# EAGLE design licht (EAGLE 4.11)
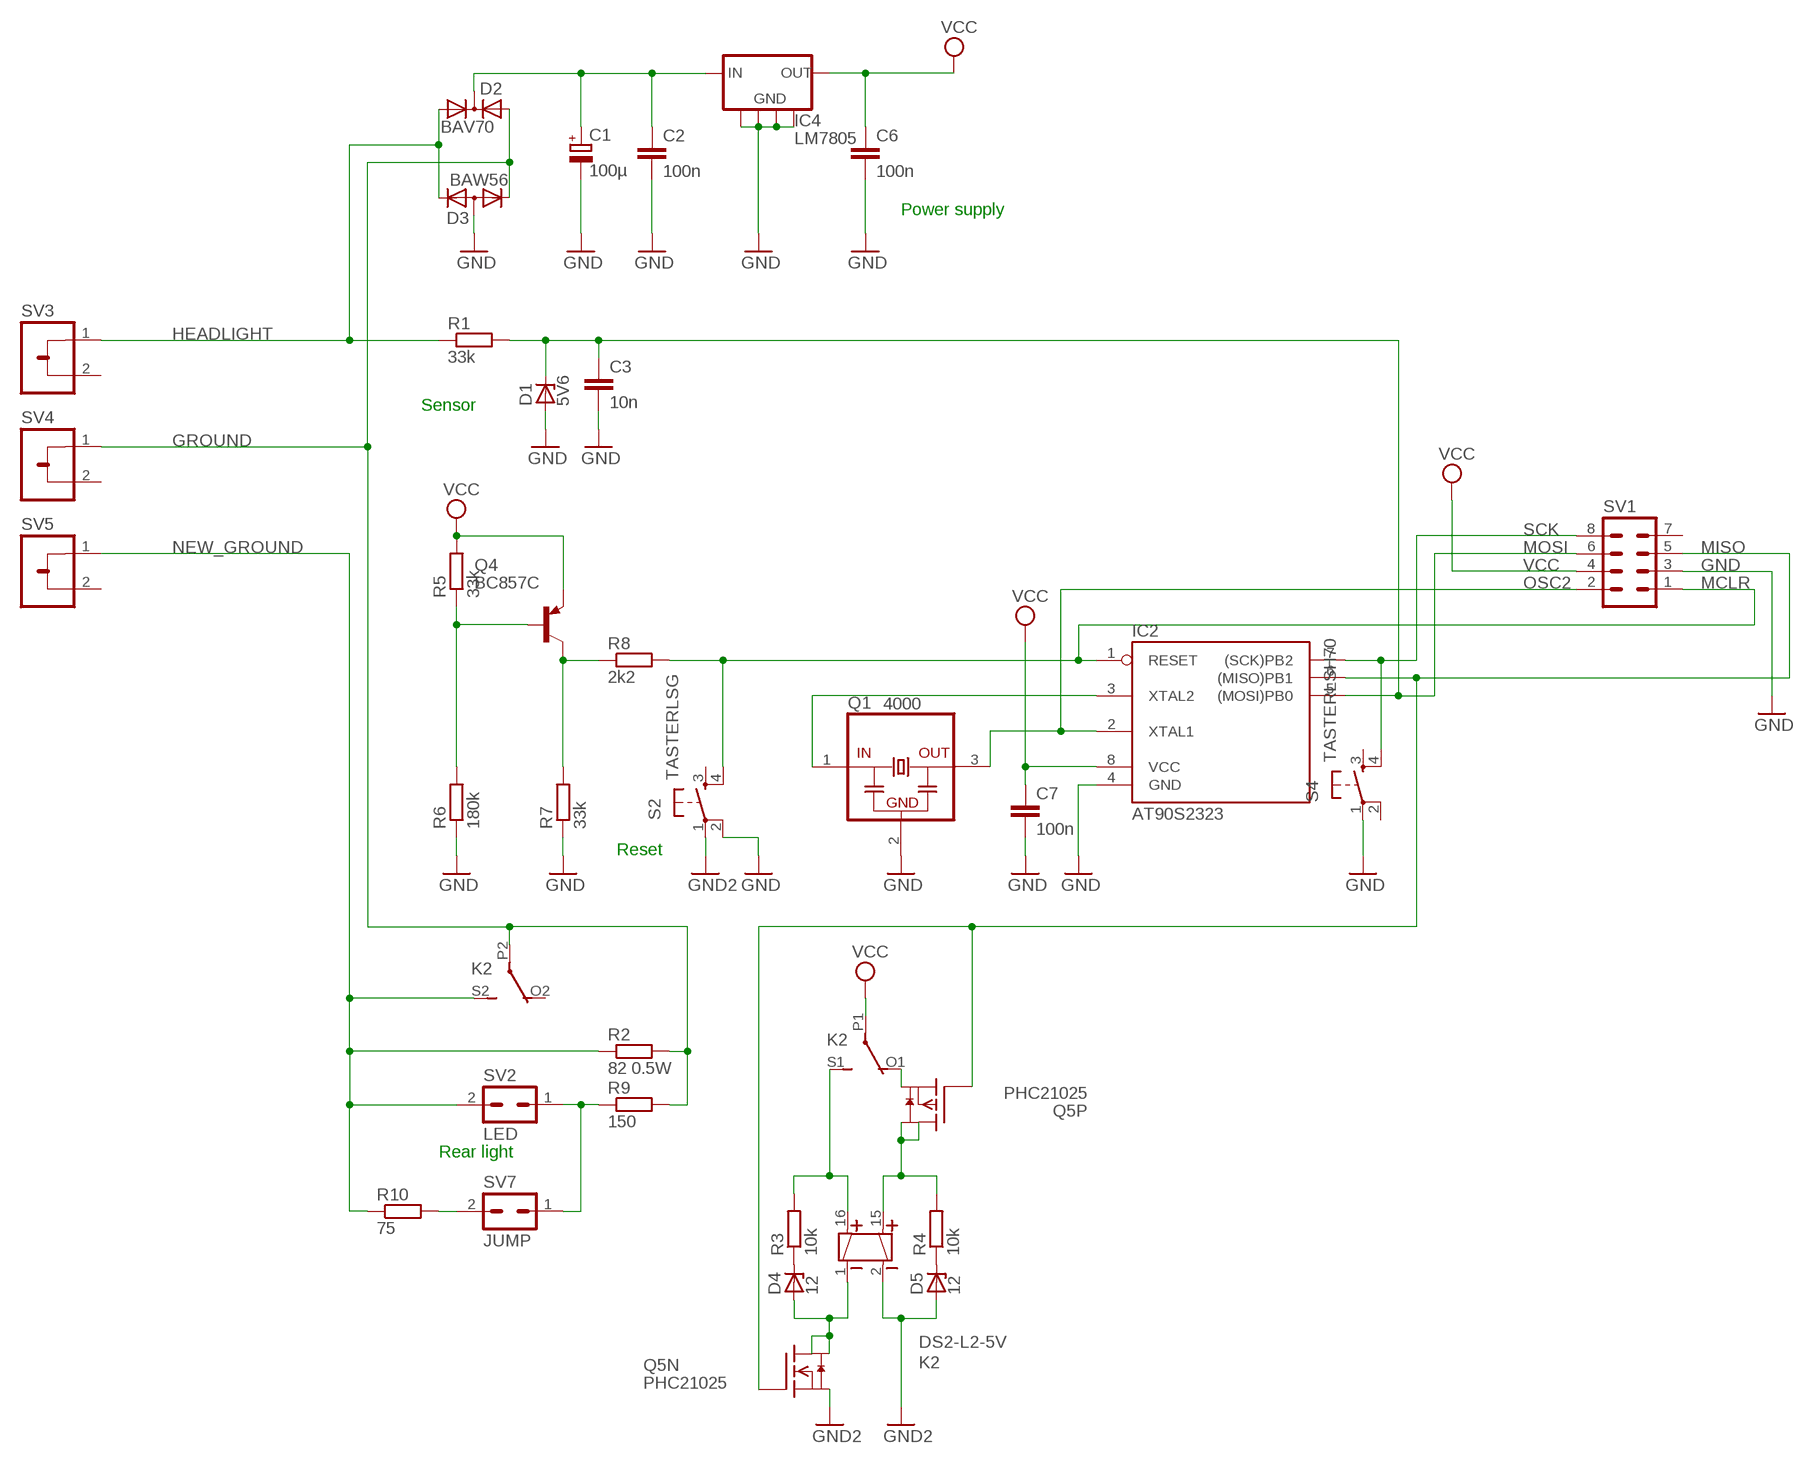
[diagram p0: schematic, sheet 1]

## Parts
C1  100µ  CPOL-EU153CLV-0605  [153CLV-0605]
C2  100n  C-EUC0603K  [C0603K]
C3  10n  C-EUC0603K  [C0603K]
C6  100n  C-EUC0603K  [C0603K]
C7  100n  C-EUC0603K  [C0603K]
D1  5V6  ZENER-DIODESOD80C  [SOD80C]
D2  BAV70  DIODE-2AC|CASOT23  [SOT23]
D3  BAW56  DIODE-2CA|ACSOT23  [SOT23]
D4  12  ZENER-DIODESOD80C  [SOD80C]
D5  12  ZENER-DIODESOD80C  [SOD80C]
IC2  AT90S2323  AT90S2323S  [SOIC8]
IC4  LM7805  LM78XX  [SO08]
K2  DS2-L2-5V  [DS2E-L2]
Q1  4000  CSTCC  [CSTCC]
Q4  BC857C  BC857CSMD  [SOT23-BEC]
Q5  PHC21025  [SO08]
R1  33k  R-EU_R0805W  [R0805W]
R2  82 0.5W  R-EU_0207/7  [0207/7]
R3  10k  R-EU_R0805W  [R0805W]
R4  10k  R-EU_R0805W  [R0805W]
R5  33k  R-EU_R0805W  [R0805W]
R6  180k  R-EU_R0805W  [R0805W]
R7  33k  R-EU_R0805W  [R0805W]
R8  2k2  R-EU_R0805W  [R0805W]
R9  150  R-EU_R0805W  [R0805W]
R10  75  R-EU_R0805W  [R0805W]
S2  TASTERLSG  [LSG25]
S4  TASTERLSH70  [LSH70]
SV1  MA04-2W  [MA04-2W]
SV2  LED  MA01-2W  [MA01-2W]
SV3  FLST  [FLST]
SV4  FLST  [FLST]
SV5  FLST  [FLST]
SV7  JUMP  MA01-2WUP  [MA02-1]

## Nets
GND: C1.- C2.2 C3.2 C6.2 C7.2 D1.A D3.3(A) IC2.4(GND) IC4.2(GND) IC4.3(GND1) IC4.6(GND2) IC4.7(GND3) Q1.2(GND) R6.1 R7.1 S2.2(P1) S4.1(P) SV1.3
GND2: D5.A K2.2 Q5.1(N:S1) S2.1(P)
GROUND: D2.2(A2) D3.1(K1) K2.P2(3:P) R2.2 R9.2 SV4.1
HEADLIGHT: D2.1(A1) D3.2(K2) R1.1 SV3.1
MCLR: IC2.1(RESET) R8.2 S2.4(S1) SV1.1
MISO: IC2.6((MISO)PB1) Q5.2(N:G1) Q5.4(P:G1) SV1.5
MOSI: C3.1 D1.C IC2.5((MOSI)PB0) R1.2 SV1.6
N$1: D4.C R3.1
N$2: D5.C R4.1
N$3: Q4.B R5.1 R6.2
N$4: Q4.C R7.2 R8.1
N$5: C1.+ C2.1 D2.3(C) IC4.8(IN)
N$9: K2.16 K2.S1(2:S) R3.2
N$10: R9.1 SV2.1 SV7.1
N$11: K2.O1(2:O) Q5.3(P:S1)
N$12: K2.15 Q5.5(P:D2) Q5.6(P:D3) R4.2
N$13: D4.A K2.1 Q5.7(N:D2) Q5.8(N:D3)
N$14: R10.2 SV7.2
NEW_GROUND: K2.S2(3:S) R2.1 R10.1 SV2.2 SV5.1
OSC1: IC2.3(XTAL2) Q1.1(IN)
OSC2: IC2.2(XTAL1) Q1.3(OUT) SV1.2
SCK: IC2.7((SCK)PB2) S4.4(S1) SV1.8
VCC: C6.1 C7.1 IC2.8(VCC) IC4.1(OUT) K2.P1(2:P) Q4.E R5.2 SV1.4
Unconnected: K2.O2(3:O) S2.3(S) S4.2(P1) S4.3(S) SV1.7 SV3.2 SV4.2 SV5.2

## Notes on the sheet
- Power supply
- Sensor
- Reset
- Rear light

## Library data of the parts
C1 = rcl:CPOL-EU: POLARIZED CAPACITOR, European symbol
C2 C3 C6 C7 = rcl:C-EU: CAPACITOR, European symbol
D1 D4 D5 = diode:ZENER-DIODE: Z-Diode
D2 = diode:DIODE-2AC|CA: Dual DIODE Anode-Cathode|Cathode-Anode
D3 = diode:DIODE-2CA|AC: Dual DIODE Cathode-Anode|Anode-Cathode
IC2 = atmel:AT90*2323: MICROCONTROLLER 2 Kbytes FLASH 128 bytes SRAM 128 bytes EEPROM
IC4 = meine:LM78XX
K2 = meine:DS2-L2-*: RELAY NAiS bistable, 2 x switch, 4 A/250 V
Q1 = meine:CSTCC
Q4 = transistor-pnp:BC857*: PNP Transistror
Q5 = meine:PHC21025
R1-R10 = rcl:R-EU_: RESISTOR, European symbol
S2 S4 = meine:TASTER
SV1 = meine:MA04-2W
SV2 SV7 = meine:MA01-2W
SV3-SV5 = meine:FLST

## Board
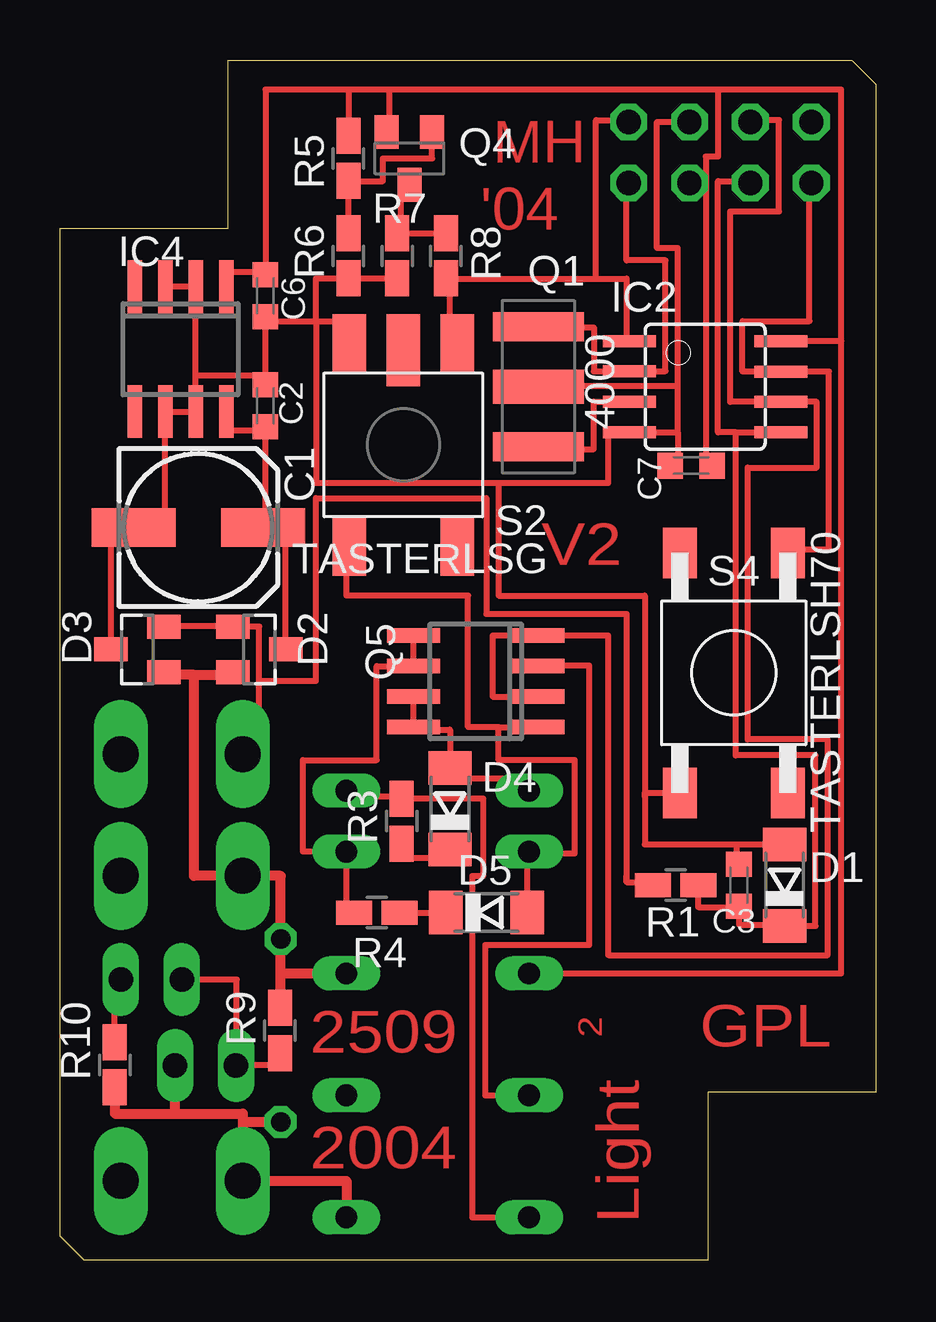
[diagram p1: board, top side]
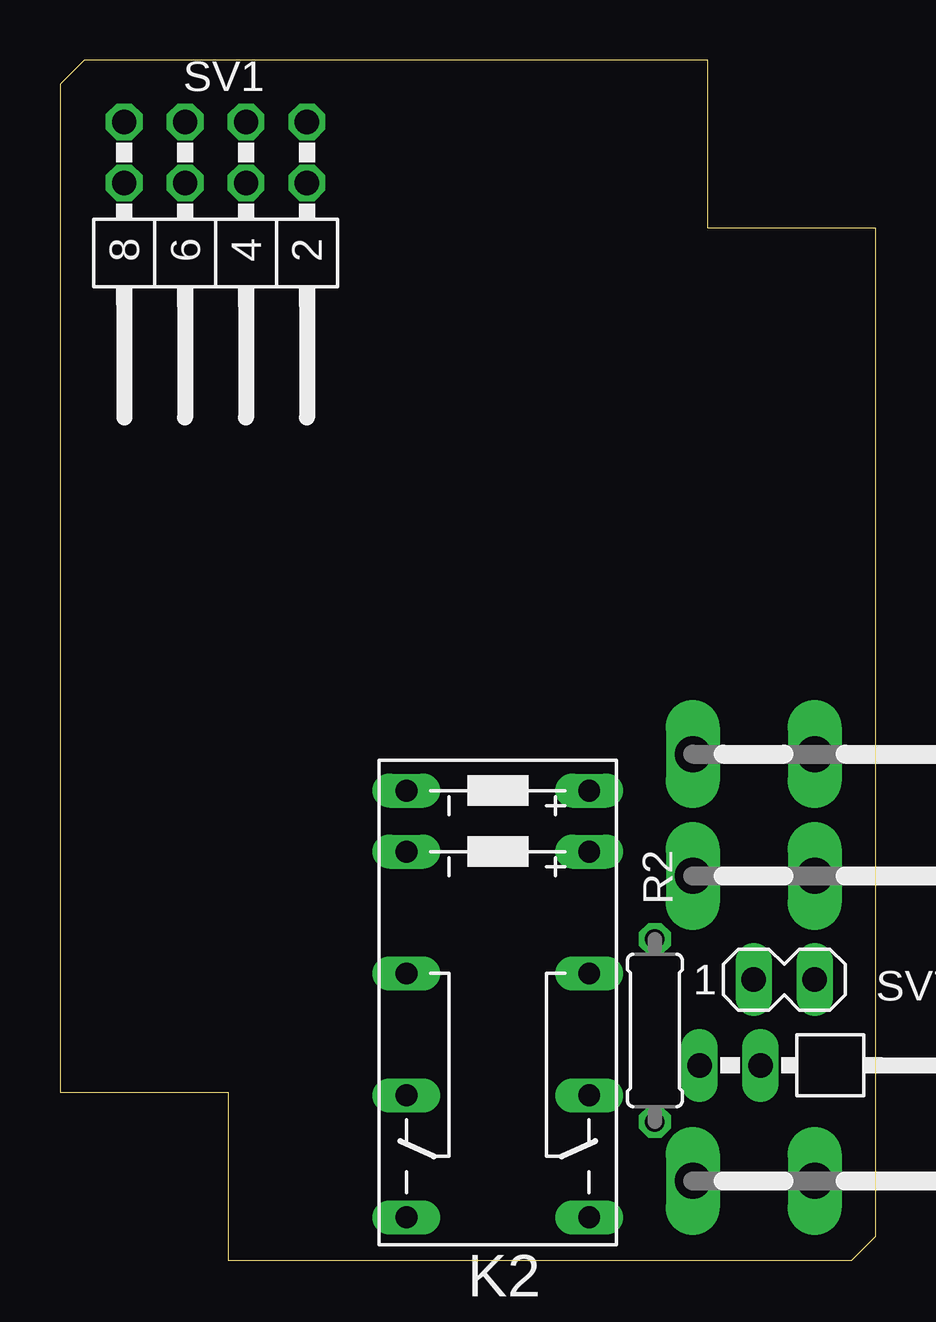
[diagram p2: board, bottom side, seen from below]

Size 34 x 50 mm. Coordinates in mm from the lower left corner, seen from the top.
Outline: 0,43 7,43 7,50 33,50 34,49 34,7 27,7 27,0 1,0 0,1 0,43
Copper layers (1*16): Top 0.035mm / dielectric 1.5mm / Bottom 0.035mm
Design rules "default": minimum track width 10mil, minimum drill 24mil, track to track 10mil, track to pad 10mil, pad to pad 10mil, via to via 10mil, smd to smd 10mil, copper to edge 40mil, drill to drill 8mil, minimum pad ring 10mil, minimum via ring 8mil, stop-mask expansion 4mil, vias tented up to drill 0mil, thermal gap 10mil

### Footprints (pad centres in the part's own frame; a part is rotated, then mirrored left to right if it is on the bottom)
153CLV-0605 = smd 3.5 x 1.6: + 2.7,0; - -2.7,0
C0603K = smd 1.05 x 1.08: 1 -0.875,0; 2 0.875,0
SOD80C = smd 1.4 x 1.8: A 1.7,0; C -1.7,0
SOT23 = smd 1 x 1.4: 1 -0.95,-1.1; 2 0.95,-1.1; 3 0,1.1
SOIC8 = smd 0.5 x 2.2: 1 -1.905,-3.154; 2 -0.645,-3.154; 3 0.625,-3.154; 4 1.895,-3.154; 5 1.905,3.154; 6 0.635,3.154; 7 -0.635,3.154; 8 -1.905,3.154
SO08 = smd 0.6 x 2.2: 1 -1.879,-2.64; 2 -0.609,-2.64; 3 0.661,-2.64; 4 1.931,-2.64; 5 1.931,2.56; 6 0.661,2.56; 7 -0.609,2.56; 8 -1.879,2.56
DS2E-L2 = drill 0.914 long: 1 -7.62,-3.81; 2 -5.08,-3.81; 15 -5.08,3.81; 16 -7.62,3.81; O1 5.08,-3.81; O2 5.08,3.81; P1 0,-3.81; P2 0,3.81; S1 10.16,-3.81; S2 10.16,3.81
CSTCC = smd 1.2 x 3.8: 1 2.5,0; 3 -2.5,0 | smd 1.4 x 3.8: 2 0,0
SOT23-BEC = smd 1 x 1.4: B -0.95,-1.1; C 0,1.1; E 0.95,-1.1
R0805W = smd 1.5 x 1: 1 -0.94,0; 2 0.94,0
0207/7 = drill 0.813 octagon: 1 -3.81,0; 2 3.81,0
LSG25 = smd 2.5 x 1.4: 1 -4.2,2.25; 2 4.2,2.25; 3 -4.2,-2.25; 4 4.2,-2.25 | smd 3 x 1.4: 5 3.95,0
LSH70 = smd 2.1 x 1.4: 1 -5,2.25; 2 5,2.25; 3 -5,-2.25; 4 5,-2.25
MA04-2W = drill 1.016 octagon: 1 -3.81,-1.27; 2 -3.81,1.27; 3 -1.27,-1.27; 4 -1.27,1.27; 5 1.27,-1.27; 6 1.27,1.27; 7 3.81,-1.27; 8 3.81,1.27
MA01-2W = drill 1.016 long: 1 0,-1.27; 2 0,1.27
FLST = drill 1.5 long: 1 0,-2.54; 2 0,2.54
MA02-1 = drill 1.016 long: 1 -1.27,0; 2 1.27,0

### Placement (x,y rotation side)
C1  5.77,30.52 0 top
C2  8.56,35.6 90 top
C3  28.31,15.62 90 top
C6  8.56,40.17 270 top
C7  26.32,33.1 180 top
D1  30.21,15.62 90 top
D2  8.31,25.44 270 top
D3  3.23,25.44 90 top
D4  16.26,18.8 90 top
D5  17.78,14.48 0 top
IC2  26.9,36.39 270 top
IC4  5.05,37.91 180 top
K2  15.75,11.94 270 bottom
Q1  19.95,36.39 270 top
Q4  14.57,45.9 180 top
Q5  17.3,24.08 90 top
R1  25.67,15.62 0 top
R2  9.2,9.56 90 bottom
R3  14.25,18.29 90 top
R4  13.21,14.48 180 top
R5  12.03,45.9 90 top
R6  12.03,41.84 90 top
R7  14.06,41.84 90 top
R8  16.09,41.84 270 top
R9  9.18,9.56 90 top
R10  2.29,8.13 90 top
S2  14.31,33.96 90 top
S4  28.09,24.47 90 top
SV1  27.51,46.15 180 bottom
SV2  6.07,8.11 270 bottom
SV3  5.08,21.08 270 bottom
SV4  5.08,16 270 bottom
SV5  5.08,3.3 270 bottom
SV7  3.81,11.68 0 bottom

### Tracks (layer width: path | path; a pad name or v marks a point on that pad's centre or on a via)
GND
  Top 0.254: 5.59,35.35 IC4.7 | 5.59,35.35 IC4.6 4.39,30.48 3.07,30.48 | 5.59,35.35 5.59,35.31 5.66,35.31 IC4.7 | 5.59,40.55 IC4.2 5.66,36.85 | 5.59,40.55 IC4.3 | 5.59,40.55 5.59,40.39 | 8.56,39.12 C6.2 | 8.56,36.85 8.56,39.12 | 8.56,36.85 C2.2 | IC4.7 5.66,36.85 | 5.66,36.85 8.56,36.85 | 3.07,30.48 C1.- | D3.3 2.13,30.48 3.07,30.48 | R7.1 R6.1 10.67,40.9 10.67,39.12 | 19.95,36.58 20.07,36.58 20.07,36.4 | 25.76,36.4 20.07,36.4 | 10.67,39.12 10.67,32.38 18.29,32.38 | C3.2 28.19,16.49 28.19,17.32 | 28.19,17.32 D1.A | 20.07,36.39 20.07,36.32 | 20.07,36.39 Q1.2 | 20.07,36.4 20.07,36.39 | 25.4,33.12 25.4,33.1 C7.2 25.76,33.1 | 24.38,19.3 24.38,27.69 18.29,27.69 18.29,32.38 | 24.38,19.3 24.38,17.32 28.19,17.32 | 18.29,32.38 22.86,32.38 22.86,34.54 23.62,34.54 23.62,34.49 IC2.4 25.76,34.49 | S4.1 24.38,19.47 24.38,19.3 | SV1.3 24.89,47.42 24.89,42.16 25.76,42.16 25.76,36.4 | 25.76,33.1 25.76,32.97 | 25.76,34.49 25.76,36.4 | 25.76,34.49 25.76,33.1 | 11.94,38.1 12.06,38.1 S2.2 11.94,38.16 11.94,38.1 | 8.56,39.12 10.67,39.12 | 10.67,39.12 11.94,39.12 11.94,38.1
GND2
  Top 0.254: D5.A 19.48,16.76 19.56,16.76 K2.2 19.56,16.94 21.46,16.94 21.46,20.83 18.29,20.83 18.29,22.2 | 18.29,22.2 17.02,22.2 17.02,27.69 11.94,27.69 11.94,29.72 12.06,29.72 S2.1 | 18.29,22.2 Q5.1
GROUND
  Top 0.254: 7.21,24.38 D2.2 | 4.33,24.38 D3.1 | 9.18,10.41 9.14,10.41 | R9.2 9.18,10.41 | 9.18,10.41 9.2,10.41
  Top 0.406: 5.59,24.38 4.33,24.38 | 5.59,24.38 7.21,24.38 | 5.59,24.38 5.59,16 SV4.1 9.2,16 R2.2 9.2,11.94 | 9.2,10.41 9.2,11.94 | 9.2,11.94 K2.P2
HEADLIGHT
  Top 0.254: D3.2 4.33,26.42 7.21,26.42 D2.1 8.31,26.39 8.31,24.13 | 8.31,24.13 8.31,21.08 SV3.1 | R1.1 24.64,15.62 24.64,15.75 23.62,15.75 | 8.31,24.13 10.67,24.13 10.67,31.75 17.78,31.75 17.78,26.92 23.62,26.92 23.62,15.75 | 23.62,15.75 23.62,16
MCLR
  Top 0.254: IC2.1 23.62,38.29 23.62,40.89 22.35,40.89 | 16,40.89 16,40.9 R8.2 | 16,40.89 22.35,40.89 | 16,40.89 16.26,40.89 16.26,38.16 | S2.4 16.26,38.16 | 16.26,38.16 16.26,38.1 | SV1.1 23.7,47.5 22.35,47.5 22.35,40.89
MISO
  Top 0.254: 28.68,32.89 28.68,21.7 32,21.7 32,12.7 22.86,12.7 22.86,26.01 Q5.4 18.03,26.01 18.03,23.47 Q5.2 | 28.68,32.89 28.68,32.94 | 28.68,32.89 28.68,33.02 31.55,33.02 31.55,35.75 IC2.6 27.94,35.75 27.94,43.69 29.97,43.69 29.97,47.5 28.7,47.5 28.7,47.42 SV1.5
MOSI
  Top 0.254: 28.17,33.86 28.17,34.34 | 28.17,34.48 IC2.5 | 28.17,33.86 28.17,34.48 | 28.31,14.71 28.37,14.71 | 28.31,14.71 C3.1 28.31,13.97 30.21,13.97 | R1.2 26.61,14.71 28.31,14.71 | 30.21,13.97 30.25,13.97 | 30.21,13.97 D1.C 31.5,13.92 31.5,21.03 28.17,21.03 28.17,33.86 | 28.17,34.48 27.43,34.48 27.43,44.96 28.7,44.96 28.7,44.88 SV1.6
N$1
  Top 0.254: D4.C 16.26,16.76 14.25,16.76 R3.1
N$2
  Top 0.254: 16.26,14.48 D5.C R4.1
N$3
  Top 0.254: R6.2 12.03,42.67 | 12.03,42.67 R5.1 13.46,44.96 13.46,45.9 15.52,45.9 Q4.B | 12.03,42.67 11.94,42.67
N$4
  Top 0.254: 14.22,42.78 14.22,42.67 | R7.2 14.22,42.78 | Q4.C 14.22,44.8 14.22,42.78 | 16,42.78 R8.1 | 14.22,42.78 16,42.78 | 16,42.78 16,42.93
N$5
  Top 0.254: 8.56,34.54 8.64,34.54 | 8.56,34.54 C2.1 8.56,30.48 | IC4.8 6.93,34.54 8.56,34.54 | 8.47,30.48 8.56,30.48 | 8.56,30.48 8.64,30.48 | D2.3 9.41,30.48 8.38,30.48 | 8.38,30.48 8.47,30.48 | 8.47,30.48 C1.+ | 8.38,30.48 7.87,30.48
N$9
  Top 0.254: K2.16 11.94,19.3 14.25,19.3 R3.2 17.65,19.23 17.65,16 17.2,16 17.2,1.78 K2.S1
N$10
  Top 0.254: R9.1 9.18,8.13 7.37,8.13 | 7.37,8.13 7.34,8.13 SV2.1 7.37,8.11 7.37,8.13 | SV7.1 7.37,11.68 7.37,8.13
N$11
  Top 0.254: Q5.3 20.07,24.74 20.04,24.77 22.07,24.77 22.07,13.13 17.73,13.13 17.73,6.86 K2.O1
N$12
  Top 0.254: 14.74,24.89 Q5.6 13.21,24.74 13.21,20.83 10.13,20.83 10.13,17.02 K2.15 11.94,14.48 R4.2 | 14.74,24.89 Q5.5 | 14.74,24.89 14.73,24.89
N$13
  Top 0.254: Q5.8 14.74,22.1 | 14.74,22.1 Q5.7 | 14.74,22.1 14.73,22.1 | 16.26,20.07 19.56,20.07 K2.1 | 16.26,20.07 D4.A | 14.74,22.1 16.26,22.1 16.26,20.07
N$14
  Top 0.254: 2.29,8.89 R10.2 2.29,11.68 SV7.2
NEW_GROUND
  Top 0.406: 7.62,5.75 R2.1 | 7.62,5.75 SV5.1 11.94,3.3 K2.S2 | 4.8,6.1 SV2.2 | 4.8,6.1 2.29,6.1 R10.1 | 4.8,6.1 7.62,6.1 7.62,5.75
OSC1
  Top 0.254: IC2.3 22.25,35.76 22.25,33.78 20.83,33.78 20.83,34.04 20.07,34.04 20.07,33.89 | 20.07,33.89 20.07,33.78 | Q1.1 20.07,33.89
OSC2
  Top 0.254: Q1.3 20.07,38.89 20.07,38.86 22.25,38.86 22.25,37.03 IC2.2 23.88,37.03 25.25,37.03 25.25,41.66 23.62,41.66 23.62,44.88 SV1.2
SCK
  Top 0.254: 30.48,29.47 30.48,29.46 | S4.4 30.48,29.47 | 30.48,29.47 30.48,29.62 32.05,29.62 32.05,37.02 IC2.7 28.45,37.02 28.45,39.12 31.24,39.12 31.24,44.88 SV1.8
VCC
  Top 0.254: 8.56,41.15 C6.1 | IC4.1 6.93,41.15 8.56,41.15 | Q4.E 13.72,47 | 27.43,48.77 13.72,48.77 | 13.72,48.77 13.72,47 | 8.56,41.15 8.56,48.77 12.19,48.77 | 13.72,48.77 12.19,48.77 | R5.2 12.03,48.77 12.19,48.77 | 32.56,38.3 32.56,11.94 K2.P1 | 32.56,38.3 32.56,48.77 27.43,48.77 | 13.72,47 13.72,46.99 | IC2.8 32.56,38.29 32.56,38.3 | C7.1 26.92,33.1 26.92,44.88 | 26.92,44.88 SV1.4 | 26.92,44.88 26.92,45.97 27.43,45.97 27.43,48.77

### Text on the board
Top: MH | '04 | V2 | 2 | 2509 | GPL | 2004 | Light
FlyPath: 6 5 | 7 0 | 8 -5 | 9 -5 | 10 -5 | 11 -5 | 12 -5 | 5 5 | 13 -5 | 3 5 | 4 5 | 14 -5 | 15 -5 | 2 5 | 20 -5 | 19 -5 | 18 -5 | 17 -5 | 16 -5 | 1 5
